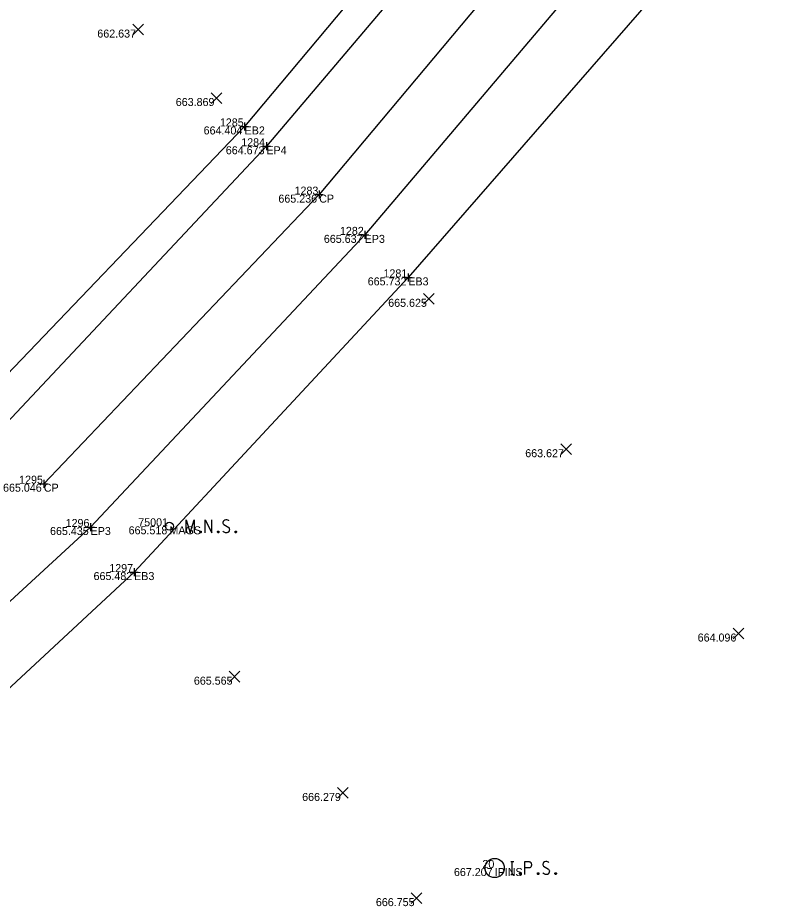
# Model space of a CAD drawing. Extents: x 2197382 to 2204062, y 634117 to 636522.
# Drawn here: x 2202854.1 to 2202947.7, y 635452.6 to 635563.6 of the extents above; entities that cross this region are included whole.
import ezdxf

# ---------------------------------------------------------------- set-up
doc = ezdxf.new("R2010")
doc.units = 0
for name, color, linetype in [('_CIVIL_CONSTRUCTION', 7, 'Continuous'), ('GE_P_Alignment_100_Distances', 7, 'Continuous'), ('GE_X_Alignment', 7, 'Continuous'), ('PV_X_COP', 7, 'Continuous'), ('RW_X_CL_100_Curve_Data', 7, 'Continuous'), ('SC_Scratch1', 7, 'Continuous'), ('SH_Border', 7, 'Continuous'), ('SH_Cut_Line', 7, 'Continuous'), ('SH_Data', 7, 'Continuous'), ('SV_P_Control_Cells_Set', 7, 'Continuous')]:
    doc.layers.add(name, color=color, linetype=linetype)

msp = doc.modelspace()

# ---------------------------------------------------------------- linework, layer by layer
at = {"layer": '_CIVIL_CONSTRUCTION'}
for p, q in [((2202881.91, 635550.01), (2202882.91, 635550.01)), ((2202882.41, 635550.51), (2202882.41, 635549.51)), ((2202882.41, 635550.01), (2202882.41, 635550.01)), ((2202884.63, 635547.53), (2202885.63, 635547.53)), ((2202885.13, 635548.03), (2202885.13, 635547.03)), ((2202885.13, 635547.53), (2202885.13, 635547.53)), ((2202891.73, 635541.99), (2202891.73, 635540.99)), ((2202891.23, 635541.49), (2202892.23, 635541.49)), ((2202891.73, 635541.49), (2202891.73, 635541.49)), ((2202896.91, 635536.46), (2202897.91, 635536.46)), ((2202897.41, 635536.96), (2202897.41, 635535.96)), ((2202897.41, 635536.46), (2202897.41, 635536.46)), ((2202902.36, 635531.15), (2202903.36, 635531.15)), ((2202902.86, 635531.65), (2202902.86, 635530.65)), ((2202902.86, 635531.15), (2202902.86, 635531.15)), ((2202856.83, 635505.37), (2202857.83, 635505.37)), ((2202857.33, 635505.87), (2202857.33, 635504.87)), ((2202857.33, 635505.37), (2202857.33, 635505.37)), ((2202862.67, 635499.96), (2202863.67, 635499.96)), ((2202863.17, 635500.46), (2202863.17, 635499.46)), ((2202863.17, 635499.96), (2202863.17, 635499.96)), ((2202868.11, 635494.33), (2202869.11, 635494.33)), ((2202868.61, 635494.83), (2202868.61, 635493.83)), ((2202868.61, 635494.33), (2202868.61, 635494.33))]:
    msp.add_line(p, q, dxfattribs=at)
at = {"layer": 'GE_P_Alignment_100_Distances'}
msp.add_line((2202863.17, 635499.96), (2202838.83, 635477.54), dxfattribs=at)
for points in [[(2203324.48, 636507.85), (2203318.62, 636484.14), (2203306.91, 636435.63), (2203294.22, 636387.53), (2203281.02, 636340.01), (2203266.86, 636291.74), (2203251.88, 636244.73), (2203235.99, 636197.91), (2203219.31, 636150.6), (2203201.96, 636104.73), (2203183.73, 636058.36), (2203164.29, 636012.58), (2203144.31, 635966.64), (2203123.63, 635921.48), (2203102.28, 635876.46), (2203085.37, 635841.98), (2203051.94, 635779.64), (2203032.08, 635745.73), (2203005.62, 635703.58), (2202977.57, 635663.01), (2202948.44, 635623.54), (2202917.31, 635585.47), (2202885.13, 635547.53), (2202851.31, 635511.58)], [(2203340.49, 636502.89), (2203334.83, 636480.1), (2203323.13, 636431.59), (2203310.29, 636383.13), (2203297.23, 636335.04), (2203282.66, 636287.13), (2203267.38, 636239.56), (2203251.38, 636192.17), (2203234.81, 636145.08), (2203217.29, 636098.29), (2203199.14, 636051.74), (2203179.44, 636005.69), (2203159.56, 635959.77), (2203137.84, 635914.65), (2203117.45, 635869.06), (2203100.66, 635835.13), (2203066.13, 635771.41), (2203046.09, 635737.06), (2203019.37, 635694.82), (2202991.01, 635653.88), (2202961.19, 635613.48), (2202929.73, 635574.61), (2202897.41, 635536.46), (2202863.17, 635499.96)]]:
    msp.add_lwpolyline(points, dxfattribs=at)
at = {"layer": 'GE_X_Alignment'}
msp.add_line((2202845.85, 635473.17), (2202868.61, 635494.33), dxfattribs=at)
for points in [[(2203321.2, 636508.87), (2203315.42, 636484.99), (2203303.56, 636436.4), (2203290.91, 636388.48), (2203277.67, 636341.19), (2203263.29, 636292.83), (2203248.5, 636245.95), (2203232.65, 636199.01), (2203215.82, 636151.66), (2203198.58, 636105.93), (2203180.2, 636059.59), (2203161.3, 636014.11), (2203141.29, 635968.09), (2203120.26, 635923.09), (2203098.92, 635878.1), (2203081.73, 635843.65), (2203048.56, 635781.48), (2203029.15, 635747.49), (2203002.61, 635705.63), (2202974.64, 635665.31), (2202945.56, 635625.56), (2202914.38, 635588.2), (2202882.41, 635550.01), (2202847.99, 635514.11)], [(2203331.27, 636429.38), (2203318.29, 636380.99), (2203304.79, 636332.88), (2203290.18, 636284.77), (2203275.23, 636236.57), (2203259.29, 636189.41), (2203242.5, 636142.16), (2203224.73, 636095.35), (2203206.44, 636048.57), (2203187.1, 636002.46), (2203167.05, 635956.43), (2203145.71, 635910.9), (2203124.58, 635865.62), (2203107.54, 635831.47), (2203073.07, 635766.88), (2203053.33, 635732.69), (2203026.37, 635690.11), (2202997.51, 635648.24), (2202967.93, 635608.32), (2202935.99, 635569.18), (2202902.86, 635531.15), (2202868.61, 635494.33)]]:
    msp.add_lwpolyline(points, dxfattribs=at)
at = {"layer": 'PV_X_COP'}
msp.add_lwpolyline([(2203333.12, 636504.55), (2203327.23, 636481.85), (2203314.64, 636433.62), (2203302.94, 636385.15), (2203289.25, 636336.51), (2203274.73, 636289.23), (2203259.31, 636242.63), (2203243.41, 636195.32), (2203226.43, 636148.15), (2203210.06, 636101.18), (2203190.93, 636055.28), (2203172.74, 636008.76), (2203151.47, 635963.31), (2203132.08, 635917.44), (2203109.53, 635872.8), (2203093.5, 635838.3), (2203058.15, 635776.21), (2203038.88, 635741.65), (2203011.92, 635699.74), (2202984.39, 635657.94), (2202954.68, 635618.56), (2202923.73, 635579.74), (2202891.73, 635541.49), (2202857.33, 635505.37)], dxfattribs=at)
at = {"layer": 'RW_X_CL_100_Curve_Data'}
for p, q in [((2202868.43, 635561.44), (2202869.77, 635562.77)), ((2202868.43, 635562.77), (2202869.77, 635561.44)), ((2202878.22, 635552.89), (2202879.56, 635554.22)), ((2202878.22, 635554.22), (2202879.56, 635552.89)), ((2202904.75, 635527.8), (2202906.09, 635529.14)), ((2202904.75, 635529.14), (2202906.09, 635527.8)), ((2202921.9, 635509.01), (2202923.23, 635510.35)), ((2202921.9, 635510.35), (2202923.23, 635509.01)), ((2202943.45, 635485.98), (2202944.78, 635487.31)), ((2202943.45, 635487.31), (2202944.78, 635485.98)), ((2202880.48, 635480.59), (2202881.81, 635481.93)), ((2202880.48, 635481.93), (2202881.81, 635480.59)), ((2202894.02, 635466.06), (2202895.35, 635467.4)), ((2202894.02, 635467.4), (2202895.35, 635466.06)), ((2202903.21, 635452.92), (2202904.55, 635454.26)), ((2202903.21, 635454.26), (2202904.55, 635452.92))]:
    msp.add_line(p, q, dxfattribs=at)
at = {"layer": 'SC_Scratch1'}
for points in [[(2202915.67, 635458.15), (2202916.03, 635458.15)], [(2202915.67, 635458.15), (2202916.03, 635458.15)], [(2202915.67, 635458.15), (2202916.03, 635458.15)], [(2202915.85, 635456.55), (2202915.85, 635458.15)], [(2202915.85, 635456.55), (2202915.85, 635458.15)], [(2202915.85, 635456.55), (2202915.85, 635458.15)], [(2202917.41, 635456.55), (2202917.41, 635458.15), (2202917.94, 635458.15), (2202918, 635458.14), (2202918.08, 635458.11), (2202918.11, 635458.09), (2202918.14, 635458.06), (2202918.19, 635458), (2202918.22, 635457.93), (2202918.24, 635457.83), (2202918.24, 635457.68), (2202918.23, 635457.63), (2202918.21, 635457.56), (2202918.16, 635457.47), (2202918.12, 635457.43), (2202918.09, 635457.41), (2202918.03, 635457.38), (2202917.94, 635457.37), (2202917.41, 635457.37)], [(2202917.41, 635456.55), (2202917.41, 635458.15), (2202917.94, 635458.15), (2202918, 635458.14), (2202918.08, 635458.11), (2202918.11, 635458.09), (2202918.14, 635458.06), (2202918.19, 635458), (2202918.22, 635457.93), (2202918.24, 635457.83), (2202918.24, 635457.68), (2202918.23, 635457.63), (2202918.21, 635457.56), (2202918.16, 635457.47), (2202918.12, 635457.43), (2202918.09, 635457.41), (2202918.03, 635457.38), (2202917.94, 635457.37), (2202917.41, 635457.37)], [(2202917.41, 635456.55), (2202917.41, 635458.15), (2202917.94, 635458.15), (2202918, 635458.14), (2202918.08, 635458.11), (2202918.11, 635458.09), (2202918.14, 635458.06), (2202918.19, 635458), (2202918.22, 635457.93), (2202918.24, 635457.83), (2202918.24, 635457.68), (2202918.23, 635457.63), (2202918.21, 635457.56), (2202918.16, 635457.47), (2202918.12, 635457.43), (2202918.09, 635457.41), (2202918.03, 635457.38), (2202917.94, 635457.37), (2202917.41, 635457.37)], [(2202920.42, 635458.04), (2202920.4, 635458.06), (2202920.37, 635458.09), (2202920.27, 635458.12), (2202920.15, 635458.15), (2202920.06, 635458.15), (2202920.03, 635458.15), (2202919.88, 635458.11), (2202919.76, 635458.04), (2202919.69, 635457.93), (2202919.66, 635457.83), (2202919.66, 635457.76), (2202919.69, 635457.66), (2202919.77, 635457.57), (2202920.38, 635457.19), (2202920.43, 635457.14), (2202920.46, 635457.09), (2202920.48, 635457.01), (2202920.48, 635456.94), (2202920.47, 635456.86), (2202920.46, 635456.81), (2202920.43, 635456.75), (2202920.41, 635456.7), (2202920.39, 635456.66), (2202920.36, 635456.62), (2202920.32, 635456.6), (2202920.28, 635456.57), (2202920.25, 635456.56), (2202920.15, 635456.55), (2202919.99, 635456.55), (2202919.89, 635456.57), (2202919.75, 635456.66), (2202919.66, 635456.74)], [(2202920.42, 635458.04), (2202920.4, 635458.06), (2202920.37, 635458.09), (2202920.27, 635458.12), (2202920.15, 635458.15), (2202920.06, 635458.15), (2202920.03, 635458.15), (2202919.88, 635458.11), (2202919.76, 635458.04), (2202919.69, 635457.93), (2202919.66, 635457.83), (2202919.66, 635457.76), (2202919.69, 635457.66), (2202919.77, 635457.57), (2202920.38, 635457.19), (2202920.43, 635457.14), (2202920.46, 635457.09), (2202920.48, 635457.01), (2202920.48, 635456.94), (2202920.47, 635456.86), (2202920.46, 635456.81), (2202920.43, 635456.75), (2202920.41, 635456.7), (2202920.39, 635456.66), (2202920.36, 635456.62), (2202920.32, 635456.6), (2202920.28, 635456.57), (2202920.25, 635456.56), (2202920.15, 635456.55), (2202919.99, 635456.55), (2202919.89, 635456.57), (2202919.75, 635456.66), (2202919.66, 635456.74)], [(2202920.42, 635458.04), (2202920.4, 635458.06), (2202920.37, 635458.09), (2202920.27, 635458.12), (2202920.15, 635458.15), (2202920.06, 635458.15), (2202920.03, 635458.15), (2202919.88, 635458.11), (2202919.76, 635458.04), (2202919.69, 635457.93), (2202919.66, 635457.83), (2202919.66, 635457.76), (2202919.69, 635457.66), (2202919.77, 635457.57), (2202920.38, 635457.19), (2202920.43, 635457.14), (2202920.46, 635457.09), (2202920.48, 635457.01), (2202920.48, 635456.94), (2202920.47, 635456.86), (2202920.46, 635456.81), (2202920.43, 635456.75), (2202920.41, 635456.7), (2202920.39, 635456.66), (2202920.36, 635456.62), (2202920.32, 635456.6), (2202920.28, 635456.57), (2202920.25, 635456.56), (2202920.15, 635456.55), (2202919.99, 635456.55), (2202919.89, 635456.57), (2202919.75, 635456.66), (2202919.66, 635456.74)], [(2202915.67, 635456.55), (2202916.03, 635456.55)], [(2202915.67, 635456.55), (2202916.03, 635456.55)], [(2202915.67, 635456.55), (2202916.03, 635456.55)], [(2202916.81, 635456.76), (2202916.86, 635456.76), (2202916.9, 635456.74), (2202916.93, 635456.69), (2202916.93, 635456.62), (2202916.9, 635456.57), (2202916.86, 635456.55), (2202916.81, 635456.55), (2202916.78, 635456.57), (2202916.74, 635456.62), (2202916.74, 635456.69), (2202916.78, 635456.74), (2202916.81, 635456.76)], [(2202916.81, 635456.76), (2202916.86, 635456.76), (2202916.9, 635456.74), (2202916.93, 635456.69), (2202916.93, 635456.62), (2202916.9, 635456.57), (2202916.86, 635456.55), (2202916.81, 635456.55), (2202916.78, 635456.57), (2202916.74, 635456.62), (2202916.74, 635456.69), (2202916.78, 635456.74), (2202916.81, 635456.76)], [(2202916.81, 635456.76), (2202916.86, 635456.76), (2202916.9, 635456.74), (2202916.93, 635456.69), (2202916.93, 635456.62), (2202916.9, 635456.57), (2202916.86, 635456.55), (2202916.81, 635456.55), (2202916.78, 635456.57), (2202916.74, 635456.62), (2202916.74, 635456.69), (2202916.78, 635456.74), (2202916.81, 635456.76)], [(2202919.06, 635456.76), (2202919.11, 635456.76), (2202919.15, 635456.74), (2202919.18, 635456.69), (2202919.18, 635456.62), (2202919.15, 635456.57), (2202919.11, 635456.55), (2202919.06, 635456.55), (2202919.02, 635456.57), (2202918.99, 635456.62), (2202918.99, 635456.69), (2202919.02, 635456.74), (2202919.06, 635456.76)], [(2202919.06, 635456.76), (2202919.11, 635456.76), (2202919.15, 635456.74), (2202919.18, 635456.69), (2202919.18, 635456.62), (2202919.15, 635456.57), (2202919.11, 635456.55), (2202919.06, 635456.55), (2202919.02, 635456.57), (2202918.99, 635456.62), (2202918.99, 635456.69), (2202919.02, 635456.74), (2202919.06, 635456.76)], [(2202919.06, 635456.76), (2202919.11, 635456.76), (2202919.15, 635456.74), (2202919.18, 635456.69), (2202919.18, 635456.62), (2202919.15, 635456.57), (2202919.11, 635456.55), (2202919.06, 635456.55), (2202919.02, 635456.57), (2202918.99, 635456.62), (2202918.99, 635456.69), (2202919.02, 635456.74), (2202919.06, 635456.76)], [(2202921.24, 635456.76), (2202921.29, 635456.76), (2202921.33, 635456.74), (2202921.36, 635456.69), (2202921.36, 635456.62), (2202921.33, 635456.57), (2202921.29, 635456.55), (2202921.24, 635456.55), (2202921.21, 635456.57), (2202921.17, 635456.62), (2202921.17, 635456.69), (2202921.21, 635456.74), (2202921.24, 635456.76)], [(2202921.24, 635456.76), (2202921.29, 635456.76), (2202921.33, 635456.74), (2202921.36, 635456.69), (2202921.36, 635456.62), (2202921.33, 635456.57), (2202921.29, 635456.55), (2202921.24, 635456.55), (2202921.21, 635456.57), (2202921.17, 635456.62), (2202921.17, 635456.69), (2202921.21, 635456.74), (2202921.24, 635456.76)], [(2202921.24, 635456.76), (2202921.29, 635456.76), (2202921.33, 635456.74), (2202921.36, 635456.69), (2202921.36, 635456.62), (2202921.33, 635456.57), (2202921.29, 635456.55), (2202921.24, 635456.55), (2202921.21, 635456.57), (2202921.17, 635456.62), (2202921.17, 635456.69), (2202921.21, 635456.74), (2202921.24, 635456.76)]]:
    msp.add_lwpolyline(points, dxfattribs=at)
msp.add_circle((2202913.65, 635457.35), 1.2, dxfattribs=at)
msp.add_circle((2202913.65, 635457.35), 1.2, dxfattribs=at)
msp.add_circle((2202913.65, 635457.35), 1.2, dxfattribs=at)
at = {"layer": 'SV_P_Control_Cells_Set'}
for points in [[(2202875.11, 635499.25), (2202875.11, 635500.85), (2202875.62, 635499.25), (2202876.11, 635500.85), (2202876.11, 635499.25)], [(2202877.48, 635499.25), (2202877.48, 635500.85), (2202878.31, 635499.25), (2202878.31, 635500.85)], [(2202880.46, 635500.73), (2202880.44, 635500.76), (2202880.4, 635500.78), (2202880.31, 635500.82), (2202880.18, 635500.85), (2202880.1, 635500.85), (2202880.06, 635500.85), (2202879.92, 635500.81), (2202879.8, 635500.73), (2202879.72, 635500.63), (2202879.7, 635500.53), (2202879.7, 635500.46), (2202879.72, 635500.36), (2202879.81, 635500.27), (2202880.42, 635499.89), (2202880.47, 635499.84), (2202880.49, 635499.79), (2202880.51, 635499.71), (2202880.51, 635499.64), (2202880.5, 635499.56), (2202880.49, 635499.51), (2202880.47, 635499.45), (2202880.45, 635499.4), (2202880.43, 635499.36), (2202880.39, 635499.32), (2202880.36, 635499.3), (2202880.32, 635499.27), (2202880.28, 635499.26), (2202880.18, 635499.25), (2202880.03, 635499.25), (2202879.93, 635499.27), (2202879.79, 635499.36), (2202879.7, 635499.44)], [(2202876.88, 635499.46), (2202876.93, 635499.46), (2202876.97, 635499.44), (2202877, 635499.39), (2202877, 635499.32), (2202876.97, 635499.27), (2202876.93, 635499.25), (2202876.88, 635499.25), (2202876.84, 635499.27), (2202876.81, 635499.32), (2202876.81, 635499.39), (2202876.84, 635499.44), (2202876.88, 635499.46)], [(2202879.09, 635499.46), (2202879.15, 635499.46), (2202879.18, 635499.44), (2202879.21, 635499.39), (2202879.21, 635499.32), (2202879.18, 635499.27), (2202879.15, 635499.25), (2202879.09, 635499.25), (2202879.06, 635499.27), (2202879.03, 635499.32), (2202879.03, 635499.39), (2202879.06, 635499.44), (2202879.09, 635499.46)], [(2202881.28, 635499.46), (2202881.33, 635499.46), (2202881.36, 635499.44), (2202881.4, 635499.39), (2202881.4, 635499.32), (2202881.36, 635499.27), (2202881.33, 635499.25), (2202881.28, 635499.25), (2202881.24, 635499.27), (2202881.21, 635499.32), (2202881.21, 635499.39), (2202881.24, 635499.44), (2202881.28, 635499.46)]]:
    msp.add_lwpolyline(points, dxfattribs=at)
msp.add_circle((2202873.02, 635500.05), 0.497, dxfattribs=at)

# ---------------------------------------------------------------- texts
at = {"layer": 'SH_Border'}
for s, p in [('EB2', (2202882.41, 635549.01)), ('EP4', (2202885.13, 635546.53)), ('CP', (2202891.73, 635540.49)), ('EP3', (2202897.41, 635535.46)), ('EB3', (2202902.86, 635530.15)), ('CP', (2202857.33, 635504.37)), ('EP3', (2202863.17, 635498.96)), ('MAGS', (2202873.02, 635499.05)), ('EB3', (2202868.61, 635493.33)), ('IPINS', (2202913.65, 635456.35)), ('IPINS', (2202913.65, 635456.35)), ('IPINS', (2202913.65, 635456.35))]:
    msp.add_text(s, height=1, dxfattribs=at).set_placement(p)
at = {"layer": 'SH_Cut_Line'}
for s, p in [('1285', (2202879.32, 635550.01)), ('1284', (2202881.99, 635547.53)), ('1283', (2202888.65, 635541.49)), ('1282', (2202894.32, 635536.46)), ('1281', (2202899.76, 635531.15)), ('1295', (2202854.24, 635505.37)), ('1296', (2202860.05, 635499.96)), ('75001', (2202869.12, 635500.05)), ('1297', (2202865.5, 635494.33)), ('20', (2202912.12, 635457.35)), ('20', (2202912.12, 635457.35)), ('20', (2202912.12, 635457.35))]:
    msp.add_text(s, height=1, dxfattribs=at).set_placement(p)
at = {"layer": 'SH_Data'}
for s, p in [('662.637', (2202864.01, 635561.11)), ('663.869', (2202873.81, 635552.56)), ('664.404', (2202877.29, 635549.01)), ('664.673', (2202880.06, 635546.53)), ('665.236', (2202886.63, 635540.49)), ('665.637', (2202892.31, 635535.46)), ('665.732', (2202897.79, 635530.15)), ('665.625', (2202900.35, 635527.47)), ('663.627', (2202917.47, 635508.68)), ('665.046', (2202852.23, 635504.37)), ('665.435', (2202858.1, 635498.96)), ('665.518', (2202867.92, 635499.05)), ('665.482', (2202863.54, 635493.33)), ('664.096', (2202939.01, 635485.65)), ('665.565', (2202876.07, 635480.26)), ('666.279', (2202889.6, 635465.73)), ('667.207', (2202908.56, 635456.35)), ('667.207', (2202908.56, 635456.35)), ('667.207', (2202908.56, 635456.35)), ('666.755', (2202898.81, 635452.59))]:
    msp.add_text(s, height=1, dxfattribs=at).set_placement(p)

doc.saveas('drawing.dxf')
